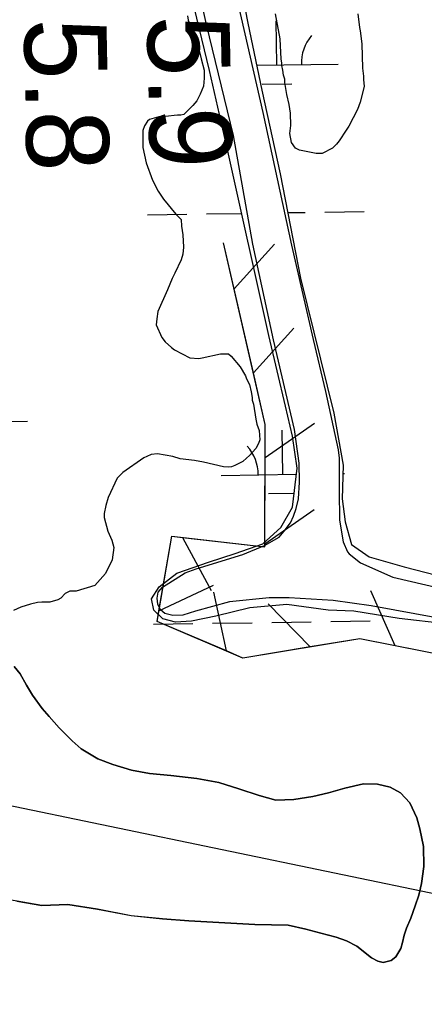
# Model space of a CAD drawing. Extents: x 3807117 to 3845308, y 337856 to 363736.
# Drawn here: x 3834019 to 3834347, y 344768 to 345575 of the extents above; entities that cross this region are included whole.
import ezdxf

# ---------------------------------------------------------------- set-up
doc = ezdxf.new("R2010")
doc.units = 0
for name, color, linetype in [('V-LEVE-TOET', 7, 'Continuous'), ('V-RIVR-EDGE', 7, 'Continuous'), ('V-RIVR-RANG', 7, 'Continuous'), ('V-RRAP-FSHR', 7, 'Continuous'), ('V-SITE-VEGE', 7, 'Continuous'), ('V-TOPO-SHOR', 7, 'Continuous'), ('V-WETL-SWMP', 7, 'Continuous')]:
    doc.layers.add(name, color=color, linetype=linetype)

msp = doc.modelspace()

# ---------------------------------------------------------------- linework, layer by layer
at = {"layer": 'V-LEVE-TOET'}
for points in [[(3834130.91, 345109.54), (3834134.44, 345113.67), (3834152.89, 345125.3), (3834161.73, 345128.46), (3834199.64, 345140.11), (3834217.31, 345147.4), (3834229.09, 345154.3), (3834233.21, 345159.22), (3834238.31, 345165.91), (3834240.86, 345171.41), (3834242.81, 345177.51), (3834244.77, 345185.37), (3834245.73, 345198.93), (3834245.31, 345214.46), (3834241.54, 345241.76), (3834224.52, 345314.44), (3834207.7, 345392.23), (3834192.04, 345480.44), (3834170.09, 345570.8), (3834153.08, 345647.41)], [(3834193.04, 345598.93), (3834215.99, 345499.15), (3834239.14, 345391.5), (3834256.75, 345314.89), (3834266.84, 345272.46), (3834277.13, 345225.11), (3834277.92, 345218.44), (3834277.77, 345191.91), (3834278.2, 345168.13), (3834281.17, 345150.45), (3834284.52, 345142.4), (3834286.1, 345140.63), (3834295.15, 345133.37), (3834321.3, 345121.82), (3834383.22, 345107.38)], [(3834358.49, 345088.47), (3834303.85, 345098.41), (3834272.99, 345102.88), (3834237.22, 345104.99), (3834221.11, 345104.96), (3834188.69, 345101.58), (3834161.2, 345094.07), (3834150.79, 345090.91), (3834142.73, 345090.7), (3834136.24, 345092.26), (3834132.7, 345095.2), (3834130.53, 345099.72), (3834129.93, 345104.63), (3834130.91, 345109.54)]]:
    msp.add_lwpolyline(points, dxfattribs=at)
at = {"layer": 'V-RIVR-EDGE'}
msp.add_spline([(3833993.63, 346073.15), (3834014.82, 346049.13), (3834027.93, 346045.03), (3834044.2, 346044.54), (3834056.42, 346046.77), (3834063.2, 346046.75), (3834065.46, 346045.39), (3834066.76, 346025.04), (3834070.78, 346004.68), (3834083.34, 345964.41), (3834083.78, 345960.79), (3834080.16, 345959.89), (3834071.58, 345963.98), (3834066.61, 345963.09), (3834057.1, 345958.14), (3834056.17, 345945.94), (3834053.89, 345939.61), (3834045.29, 345936.01), (3834032.17, 345933.79), (3834020.87, 345934.27), (3834010.46, 345930.67), (3833991.44, 345919.42), (3833968.34, 345903.65), (3833937.09, 345880.21), (3833918.03, 345855.85), (3833899.87, 345825.6), (3833887.57, 345788.55), (3833879.36, 345756.47), (3833874.27, 345710.36), (3833869.21, 345675.1), (3833852.34, 345618.62), (3833845.48, 345588.35), (3833842.69, 345557.15), (3833837.61, 345515.12), (3833834.32, 345463.13), (3833833.31, 345422.89), (3833835.49, 345389.87), (3833826.75, 345327.5), (3833812.58, 345266.04), (3833811.6, 345236.2), (3833805.63, 345198.23), (3833800.11, 345162.07), (3833798.68, 345131.78), (3833801.81, 345114.59), (3833810.79, 345092.41), (3833826.56, 345068.41), (3833838.72, 345048.94), (3833853.17, 345041.22), (3833864.45, 345032.14), (3833872.11, 345019.46), (3833872.08, 345008.16), (3833866.05, 344947.59), (3833859.08, 344872.55), (3833858.17, 344868.03), (3833853.65, 344868.04), (3833833.32, 344878.03), (3833815.73, 344894.81), (3833804.91, 344906.14), (3833797.68, 344908.87), (3833783.21, 344908.45), (3833736.6, 344893.2), (3833706.24, 344865.69), (3833687.65, 344845.39), (3833676.3, 344827.33), (3833665.38, 344800.68), (3833650.83, 344767.71), (3833632.62, 344715.75), (3833615.31, 344663.8), (3833598.93, 344623.14), (3833579.38, 344582.5), (3833566.62, 344539.57), (3833556.59, 344505.69), (3833525.62, 344416.69), (3833510.59, 344373.77), (3833496.02, 344333.11), (3833486.92, 344308.72), (3833473.26, 344271.22), (3833455.06, 344226.05), (3833441.84, 344180.87), (3833432.72, 344150.15), (3833396.31, 344055.73), (3833377.19, 344001.07), (3833358.09, 343958.61), (3833345.37, 343934.23), (3833328.05, 343879.56), (3833312.99, 343821.72), (3833296.6, 343775.64), (3833286.11, 343739.5), (3833276.03, 343687.07), (3833267.36, 343654.99), (3833255.05, 343614.32), (3833253.24, 343609.33)], degree=3, dxfattribs=at)
at = {"layer": 'V-RIVR-RANG'}
msp.add_line((3834413.93, 344852.16), (3832955.14, 345155.51), dxfattribs=at)
at = {"layer": 'V-RRAP-FSHR'}
for p, q in [((3834192.58, 345356.03), (3834225.32, 345392.26)), ((3834208.2, 345287.8), (3834240.94, 345324.03)), ((3834217.72, 345218.89), (3834257.8, 345246.77)), ((3834217.5, 345148.89), (3834257.58, 345176.77)), ((3834150.51, 345153.97), (3834173.79, 345111.04)), ((3834131.48, 345094.39), (3834175.7, 345115.12)), ((3834186.29, 345061.78), (3834176.16, 345109.55)), ((3834323.28, 345066.03), (3834303.62, 345110.73)), ((3834254.39, 345065.11), (3834220.23, 345100.01))]:
    msp.add_line(p, q, dxfattribs=at)
for points in [[(3833587.4, 344306.39), (3833655.44, 344519.24), (3833727.52, 344609.71), (3833863.55, 344726.58), (3834053.99, 344681.27), (3834173.13, 344670.35), (3834274.83, 344648.59), (3834336.9, 344641.48), (3834420.33, 345004.84), (3834419.03, 345046.97), (3834294.53, 345071.76), (3834199.74, 345056.07), (3834129.98, 345085.72), (3834142.03, 345154.94), (3834217.49, 345146.3), (3834217.8, 345245.84), (3834184.05, 345393.3)], [(3834208.2, 345287.8), (3834185.12, 345388.63)], [(3834217.72, 345218.89), (3834217.8, 345245.84), (3834208.2, 345287.8)], [(3834217.5, 345148.89), (3834217.72, 345218.89)], [(3834131.48, 345094.39), (3834142.03, 345154.94), (3834150.51, 345153.97)], [(3834150.51, 345153.97), (3834217.49, 345146.3), (3834217.5, 345148.89)], [(3834186.29, 345061.78), (3834129.98, 345085.72), (3834131.48, 345094.39)], [(3834323.28, 345066.03), (3834294.53, 345071.76), (3834254.39, 345065.11)], [(3834254.39, 345065.11), (3834199.74, 345056.07), (3834186.29, 345061.79)], [(3834391.93, 345052.37), (3834323.28, 345066.03)]]:
    msp.add_lwpolyline(points, dxfattribs=at)
at = {"layer": 'V-SITE-VEGE'}
for points in [[(3834154.7, 345577.85), (3834155.17, 345574.16), (3834163.04, 345553.89), (3834165.35, 345545.14), (3834165.82, 345542.84), (3834168.14, 345533.62), (3834168.15, 345527.17), (3834167.7, 345520.72), (3834164.94, 345514.26), (3834162.18, 345508.72), (3834158.96, 345505.03), (3834151.6, 345497.64)], [(3834292.97, 345579.44), (3834294.37, 345568.38), (3834294.84, 345565.62), (3834296.24, 345555.02), (3834296.73, 345535.2), (3834297.66, 345528.75), (3834297.67, 345525.98), (3834298.13, 345520.45), (3834294.93, 345507.54), (3834292.63, 345501.55), (3834285.74, 345488.17), (3834283.44, 345484.94), (3834277.92, 345476.17), (3834275.62, 345473.41), (3834272.4, 345470.18), (3834264.11, 345466.02), (3834259.04, 345466.01), (3834245.67, 345468.75), (3834242.44, 345470.13), (3834239.21, 345474.73), (3834237.81, 345482.11), (3834238.73, 345488.56), (3834238.25, 345498.7), (3834237.32, 345505.61), (3834235.46, 345513.91), (3834233.6, 345523.58), (3834233.6, 345526.35), (3834232.67, 345529.57), (3834232.21, 345533.72), (3834231.28, 345537.4), (3834231.27, 345539.71), (3834230.81, 345542.48), (3834229.86, 345559.07), (3834226.14, 345579.34)], [(3834151.6, 345497.64), (3834149.3, 345497.18), (3834146.53, 345497.18), (3834143.77, 345496.71), (3834134.55, 345495.77), (3834131.32, 345495.77), (3834123.95, 345493.45), (3834122.11, 345492.07), (3834119.81, 345488.38), (3834118.43, 345484.69), (3834118.46, 345470.86), (3834121.24, 345458.42), (3834126.33, 345444.14), (3834130.96, 345435.39), (3834135.11, 345428.94), (3834145.27, 345416.51), (3834149.43, 345412.37), (3834149.9, 345406.84), (3834150.83, 345399.93), (3834151.31, 345389.79), (3834150.85, 345384.26), (3834149.48, 345379.65), (3834144.42, 345368.58), (3834142.13, 345364.43), (3834138.45, 345355.2), (3834130.64, 345337.68), (3834129.73, 345331.68), (3834129.28, 345326.61)], [(3834129.28, 345326.61), (3834133.9, 345316.48), (3834136.68, 345312.8), (3834141.75, 345308.2), (3834144.06, 345306.36), (3834156.51, 345299.92), (3834163.89, 345299.47), (3834166.65, 345299.94), (3834181.4, 345303.19), (3834187.85, 345303.2), (3834190.16, 345301.36), (3834197.54, 345292.61), (3834201.7, 345285.24), (3834202.63, 345282.94), (3834204.94, 345278.33), (3834206.33, 345272.34), (3834207.26, 345267.74), (3834207.26, 345265.43), (3834208.19, 345262.21), (3834210.05, 345250.23), (3834210.98, 345246.08), (3834212.83, 345241.01), (3834213.31, 345233.18), (3834212.39, 345230.41), (3834210.09, 345226.26), (3834205.03, 345220.72), (3834202.73, 345218.41), (3834199.5, 345215.64), (3834193.06, 345212.41), (3834190.29, 345211.48), (3834187.99, 345211.02), (3834183.84, 345211.47), (3834167.7, 345215.13), (3834160.33, 345216.51), (3834148.8, 345217.87), (3834142.81, 345219.7), (3834130.36, 345221.99), (3834125.29, 345221.52), (3834121.61, 345219.67), (3834119.3, 345218.74), (3834102.27, 345206.74), (3834097.67, 345202.12), (3834090.31, 345186.44), (3834088.48, 345179.98), (3834087.11, 345173.53), (3834087.11, 345170.3), (3834089.9, 345159.24), (3834093.13, 345151.87), (3834094.99, 345145.89), (3834093.62, 345135.74), (3834088.11, 345124.67), (3834079.36, 345114.98), (3834064.16, 345110.35), (3834059.09, 345110.34), (3834055.41, 345108.49), (3834051.72, 345104.8), (3834049.42, 345103.41), (3834042.97, 345101.56), (3834036.52, 345101.55), (3834032.83, 345101.08), (3834027.3, 345099.69), (3834019.47, 345097.38), (3834013.48, 345094.6)]]:
    msp.add_lwpolyline(points, dxfattribs=at)
at = {"layer": 'V-TOPO-SHOR'}
for points in [[(3834057.58, 344855.95), (3834081.66, 344852.04), (3834108.89, 344846.76), (3834134.33, 344844.27), (3834155.64, 344842.53), (3834209.3, 344839.65), (3834236.33, 344838.9), (3834250.73, 344835.77), (3834262.97, 344832.63), (3834275.4, 344829.29), (3834283.89, 344826.35), (3834292.18, 344822.02), (3834296.33, 344818.67), (3834304.03, 344812.38), (3834309.16, 344809.82), (3834313.7, 344808.64), (3834320.01, 344810.42), (3834323.75, 344813.19), (3834327.89, 344820.1), (3834329.26, 344825.04), (3834330.63, 344830.96), (3834332.6, 344836.48), (3834335.93, 344844.77), (3834339.67, 344854.84), (3834342.62, 344863.33), (3834344.77, 344872.8), (3834346.72, 344886.81), (3834346.3, 344902.98), (3834343.32, 344917.18), (3834340.94, 344926.25), (3834335.2, 344938.47), (3834327.69, 344946.55), (3834319.4, 344951.27), (3834308.94, 344953.62), (3834297.5, 344953.8), (3834282.32, 344950.23), (3834269.11, 344946.46), (3834256.49, 344943.48), (3834240.91, 344941.09), (3834226.51, 344940.48), (3834212.89, 344944.4), (3834196.31, 344949.9), (3834180.13, 344954.8), (3834162.37, 344958.13), (3834141.06, 344960.66), (3834123.9, 344962.22), (3834109.1, 344964.95), (3834094.1, 344969.47), (3834081.86, 344974.18), (3834068.44, 344982.25), (3834060.93, 344988.75), (3834050.46, 344999.38), (3834042.28, 345008.68), (3834036.75, 345015.18), (3834028.72, 345025.94), (3834023.97, 345034.02), (3834018.79, 345043.21), (3834014.05, 345049.2)], [(3834016.07, 344858.51), (3834036.3, 344855.13), (3834057.58, 344855.95)]]:
    msp.add_lwpolyline(points, dxfattribs=at)
at = {"layer": 'V-WETL-SWMP'}
for p, q in [((3834195.83, 345610.91), (3834203.79, 345571.79)), ((3834172.63, 345533.4), (3834157.51, 345595.43)), ((3834203.79, 345571.79), (3834214.94, 345517.26)), ((3834227.17, 345537.83), (3834226.63, 345573.82)), ((3834210.79, 345537.58), (3834277.16, 345538.57)), ((3834187.35, 345467.82), (3834172.63, 345533.4)), ((3834215.4, 345522.22), (3834239.4, 345522.58)), ((3834214.94, 345517.26), (3834230.06, 345449.31)), ((3834220.78, 345318.08), (3834187.35, 345467.82)), ((3834230.06, 345449.31), (3834246.4, 345364.75)), ((3834122.13, 345416.17), (3834154.13, 345416.65)), ((3834170.13, 345416.89), (3834198.63, 345417.31)), ((3834236.14, 345417.88), (3834250.12, 345418.08)), ((3834266.12, 345418.32), (3834298.11, 345418.8)), ((3834246.4, 345364.75), (3834273.44, 345254.92)), ((3834234.31, 345260.79), (3834220.78, 345318.08)), ((3834239.88, 345236.29), (3834234.31, 345260.79)), ((3834273.44, 345254.92), (3834281.02, 345212.64)), ((3833992.64, 345248.03), (3834024.63, 345248.51)), ((3834232.15, 345205.19), (3834231.61, 345241.18)), ((3834243.87, 345210.21), (3834239.88, 345236.29)), ((3834182.16, 345204.44), (3834243.27, 345205.35)), ((3834239.96, 345178.59), (3834243.87, 345210.21)), ((3834281.02, 345212.64), (3834280.27, 345185.37)), ((3834280.83, 345205.92), (3834282.15, 345205.94)), ((3834220.38, 345189.58), (3834241.36, 345189.89)), ((3834280.27, 345185.37), (3834282.67, 345166.8)), ((3834230.5, 345161.97), (3834239.96, 345178.59)), ((3834282.67, 345166.8), (3834287.83, 345148.23)), ((3834215.9, 345148.91), (3834230.5, 345161.97)), ((3834193.38, 345140.97), (3834215.9, 345148.91)), ((3834171.66, 345133.82), (3834193.38, 345140.97)), ((3834287.83, 345148.23), (3834302.08, 345138.37)), ((3834145.98, 345125.09), (3834171.66, 345133.82)), ((3834302.08, 345138.37), (3834330.55, 345130.11)), ((3834131.77, 345114), (3834145.98, 345125.09)), ((3834330.55, 345130.11), (3834365.34, 345121.08)), ((3834125.46, 345104.11), (3834131.77, 345114)), ((3834127.45, 345095.02), (3834125.46, 345104.11)), ((3834134.58, 345087.92), (3834127.45, 345095.02)), ((3834205.31, 345096.72), (3834177.65, 345089.96)), ((3834235.34, 345099.53), (3834205.31, 345096.72)), ((3834268.94, 345094.84), (3834235.34, 345099.53)), ((3834289.89, 345094.09), (3834268.94, 345094.84)), ((3834326.66, 345088.21), (3834289.89, 345094.09)), ((3834144.86, 345085.17), (3834134.58, 345087.92)), ((3834157.9, 345085.98), (3834144.86, 345085.17)), ((3834177.65, 345089.96), (3834157.9, 345085.98)), ((3834175.11, 345084.25), (3834207.11, 345084.73)), ((3834223.11, 345084.97), (3834255.1, 345085.45)), ((3834271.1, 345085.69), (3834303.1, 345086.17)), ((3834364.21, 345083.92), (3834326.66, 345088.21)), ((3834127.12, 345083.53), (3834159.11, 345084.01)), ((3834014.05, 345049.2), (3834018.79, 345043.21)), ((3834018.79, 345043.21), (3834023.97, 345034.02)), ((3834023.97, 345034.02), (3834028.72, 345025.94)), ((3834028.72, 345025.94), (3834036.75, 345015.18)), ((3834036.75, 345015.18), (3834042.28, 345008.68)), ((3834042.28, 345008.68), (3834050.46, 344999.38)), ((3834050.46, 344999.38), (3834060.93, 344988.75)), ((3834060.93, 344988.75), (3834068.44, 344982.25)), ((3834068.44, 344982.25), (3834081.86, 344974.18)), ((3834081.86, 344974.18), (3834094.1, 344969.47)), ((3834094.1, 344969.47), (3834109.1, 344964.95)), ((3834109.1, 344964.95), (3834123.9, 344962.21)), ((3834123.9, 344962.21), (3834141.06, 344960.66)), ((3834141.06, 344960.66), (3834162.37, 344958.13)), ((3834162.37, 344958.13), (3834180.13, 344954.8)), ((3834180.13, 344954.8), (3834196.31, 344949.9)), ((3834196.31, 344949.9), (3834212.89, 344944.4)), ((3834269.11, 344946.46), (3834282.32, 344950.23)), ((3834282.32, 344950.23), (3834297.5, 344953.8)), ((3834297.5, 344953.8), (3834308.94, 344953.62)), ((3834308.94, 344953.62), (3834319.4, 344951.27)), ((3834319.4, 344951.27), (3834327.69, 344946.55)), ((3834212.89, 344944.4), (3834226.51, 344940.47)), ((3834226.51, 344940.47), (3834240.91, 344941.09)), ((3834240.91, 344941.09), (3834256.49, 344943.48)), ((3834256.49, 344943.48), (3834269.11, 344946.46)), ((3834327.69, 344946.55), (3834335.2, 344938.47)), ((3834335.2, 344938.47), (3834340.94, 344926.25)), ((3834340.94, 344926.25), (3834343.32, 344917.18)), ((3834343.32, 344917.18), (3834346.3, 344902.98)), ((3834346.3, 344902.98), (3834346.72, 344886.81)), ((3834346.72, 344886.81), (3834344.77, 344872.8)), ((3834344.77, 344872.8), (3834342.61, 344863.33)), ((3834036.3, 344855.13), (3834010.02, 344859.55)), ((3834342.61, 344863.33), (3834339.67, 344854.84)), ((3834057.58, 344855.95), (3834036.3, 344855.13)), ((3834081.66, 344852.04), (3834057.58, 344855.95)), ((3834108.89, 344846.75), (3834081.66, 344852.04)), ((3834339.67, 344854.84), (3834335.93, 344844.77)), ((3834134.34, 344844.27), (3834108.89, 344846.75)), ((3834155.64, 344842.52), (3834134.34, 344844.27)), ((3834335.93, 344844.77), (3834332.59, 344836.48)), ((3834209.3, 344839.65), (3834155.64, 344842.52)), ((3834236.33, 344838.9), (3834209.3, 344839.65)), ((3834250.73, 344835.77), (3834236.33, 344838.9)), ((3834262.97, 344832.63), (3834250.73, 344835.77)), ((3834332.59, 344836.48), (3834330.63, 344830.96)), ((3834275.4, 344829.29), (3834262.97, 344832.63)), ((3834283.89, 344826.35), (3834275.4, 344829.29)), ((3834330.63, 344830.96), (3834329.26, 344825.04)), ((3834292.18, 344822.02), (3834283.89, 344826.35)), ((3834304.03, 344812.37), (3834292.18, 344822.02)), ((3834327.88, 344820.1), (3834323.75, 344813.19)), ((3834329.26, 344825.04), (3834327.88, 344820.1)), ((3834309.16, 344809.82), (3834304.03, 344812.37)), ((3834320.01, 344810.43), (3834313.7, 344808.64)), ((3834323.75, 344813.19), (3834320.01, 344810.43)), ((3834313.7, 344808.64), (3834309.16, 344809.82))]:
    msp.add_line(p, q, dxfattribs=at)
for centre, start, end in [((3834282.4, 345539.13), 140.08653, 181.63019), ((3834176.91, 345204.84), 0.08653, 41.63019)]:
    msp.add_arc(centre, 35.25, start, end, dxfattribs=at)

# ---------------------------------------------------------------- texts
at = {"layer": 'V-RIVR-RANG'}
for s, p in [('5.8', (3834021.82, 345575.26)), ('5.9', (3834121.79, 345577.78))]:
    msp.add_text(s, height=67, rotation=271.14833, dxfattribs=at).set_placement(p)

doc.saveas('drawing.dxf')
